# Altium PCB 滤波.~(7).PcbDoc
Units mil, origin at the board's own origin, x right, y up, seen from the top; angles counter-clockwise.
Board outline 6000 x 4000 mil, 2 copper layers (Top Layer, Bottom Layer); 19 components, 13 nets, 56 pads, 2 vias.
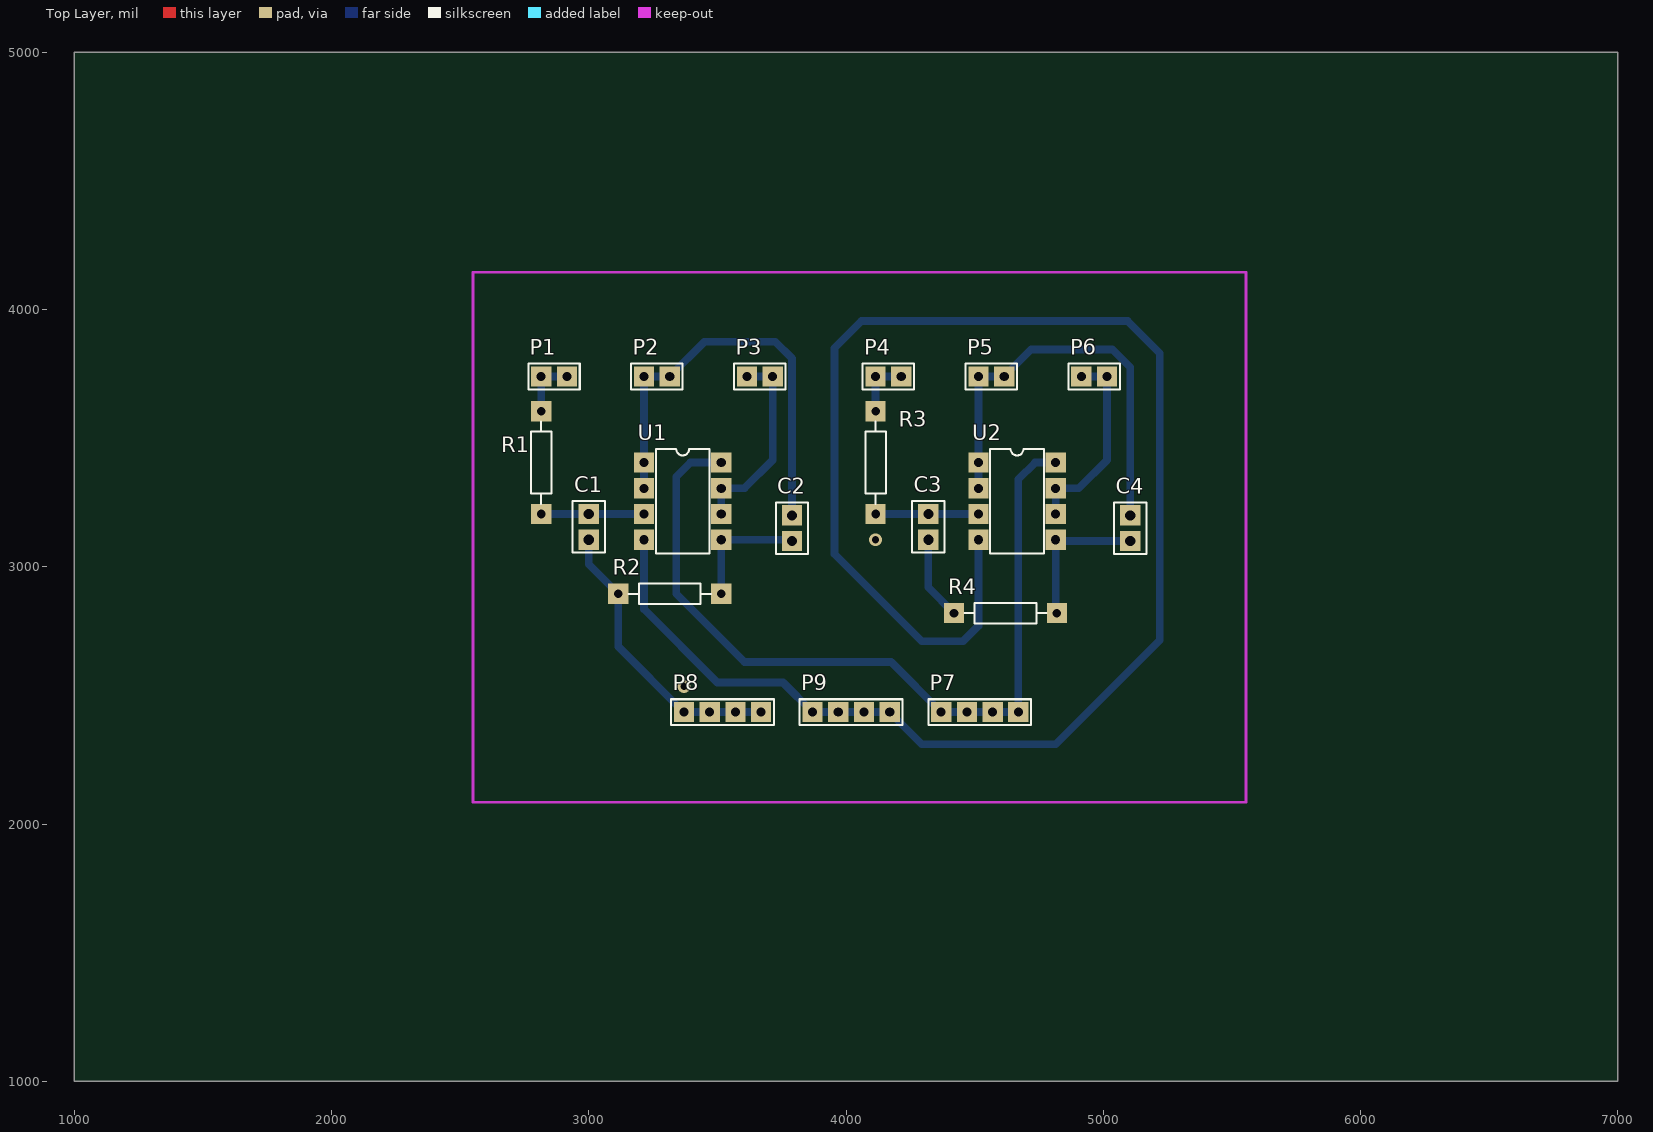
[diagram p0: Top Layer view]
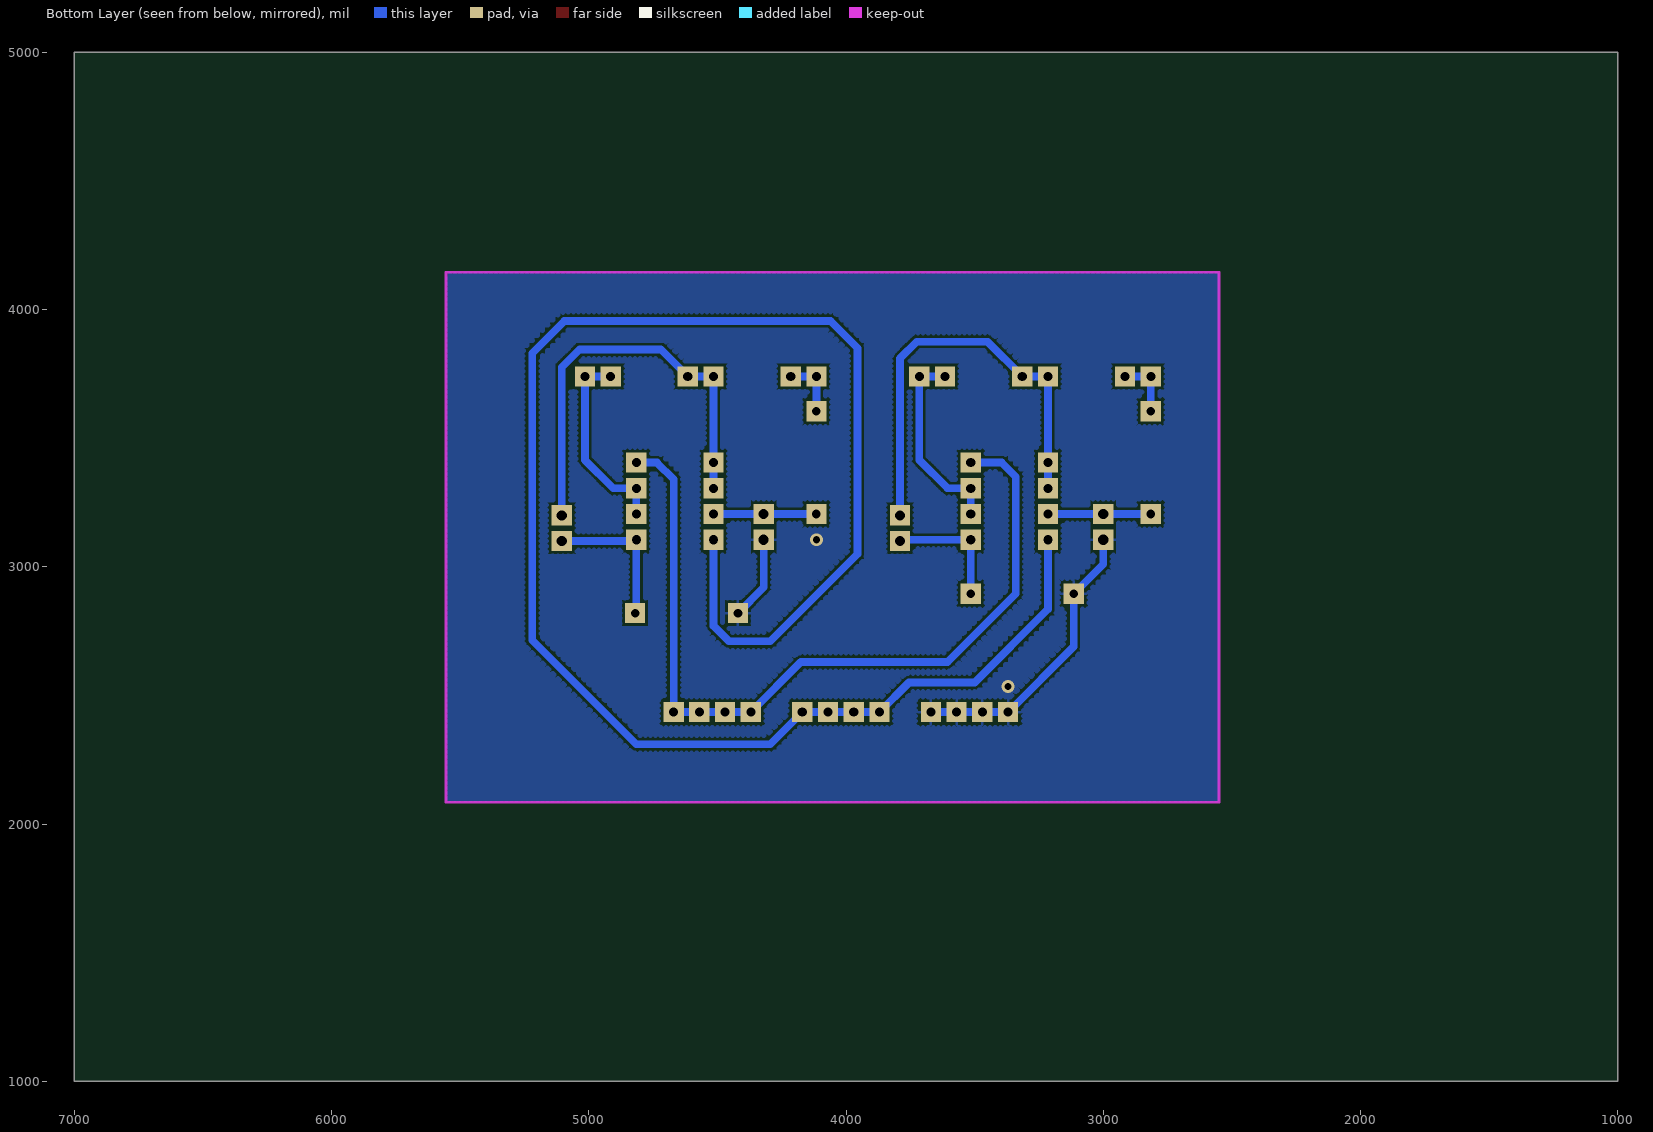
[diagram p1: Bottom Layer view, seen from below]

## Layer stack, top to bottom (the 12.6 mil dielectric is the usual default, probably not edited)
Top Layer: signal copper 1.4
Dielectric: dielectric 12.6, FR-4, Dk 4.8
Bottom Layer: signal copper 1.4

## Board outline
1000,1000 7000,1000 7000,5000 1000,5000

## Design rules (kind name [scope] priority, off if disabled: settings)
Clearance [All] p1: gap=10
PolygonConnect [All] p1: connectstyle=Relief reliefconductorwidth=10 reliefentries=4 polygonreliefangle="90 Angle" airgapwidth=10
RoutingLayers [All] p1: top layer_v5=FALSE bottom layer_v5=TRUE
RoutingVias [All] p1: holewidth=28 width=50 viastyle="Through Hole" minholewidth=28 minwidth=50 maxholewidth=28 maxwidth=50
SolderMaskExpansion [All] p1: expansion=4
Width [All] p1: maxlimit=30 minlimit=30 preferedwidth=30
27 further rules are at their usual default settings.

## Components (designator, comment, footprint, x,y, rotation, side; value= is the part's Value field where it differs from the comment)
C1 "Cap" CAPR2.54-5.1x3.2 3000,3155 r90 top
C2 "Cap" CAPR2.54-5.1x3.2 3790,3150 r270 top
C3 "Cap" CAPR2.54-5.1x3.2 4320,3155 r90 top
C4 "Cap" CAPR2.54-5.1x3.2 5105,3150 r270 top
P1 "Header 2" HDR1X2 2815,3740 r0 top
P2 "Header 2" HDR1X2 3215,3740 r0 top
P3 "Header 2" HDR1X2 3715,3740 r180 top
P4 "Header 2" HDR1X2 4215,3740 r180 top
P5 "Header 2" HDR1X2 4615,3740 r180 top
P6 "Header 2" HDR1X2 5015,3740 r180 top
P7 "Header 4" HDR1X4 4670,2435 r180 top
P8 "Header 4" HDR1X4 3670,2435 r180 top
P9 "Header 4" HDR1X4 4170,2435 r180 top
R1 "Res2" AXIAL-0.4 2815,3405 r270 top
R2 "Res2" AXIAL-0.4 3315,2895 r0 top
R3 "Res2" AXIAL-0.4 4115,3405 r270 top
R4 "Res2" AXIAL-0.4 4620,2820 r0 top
U1 "LM358N" 626-05 3365,3255 r270 top
U2 "LM358N" 626-05 4665,3255 r270 top

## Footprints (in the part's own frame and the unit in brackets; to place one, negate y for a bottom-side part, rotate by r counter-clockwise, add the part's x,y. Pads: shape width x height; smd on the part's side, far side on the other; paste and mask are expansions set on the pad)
626-05 [mm] "DIP; 8 Leads; Row Spacing 7.62 mm; Pitch 2.54 mm"
  rect 2x2 hole 0.9: 1(-3.81,-3.81) 2(-1.27,-3.81) 3(1.27,-3.81) 4(3.81,-3.81) 5(3.81,3.81) 6(1.27,3.81) 7(-1.27,3.81) 8(-3.81,3.81)
  silkscreen extent -5.15,-2.65 5.15,2.65
AXIAL-0.4 [mm] "Axial Device, Thru-Hole; 2 Leads; 0.4 in Pin Spacing"
  rect 2x2 hole 0.85: 1(-5.08,0) 2(5.08,0)
  silkscreen extent -4.06,-1.02 4.06,1.02
CAPR2.54-5.1x3.2 [mm] "Capacitor, Ceramic, Thru-Hole, Dipped Radial; Body 5.1 x 3.2 mm (WxT) Pin Spacing 2.54 mm (typ)"
  rect 2x2 hole 1: 1(-1.27,0) 2(1.27,0)
  silkscreen extent -2.55,-1.6 2.55,1.6
HDR1X2 [mm] "Connector; Header; 2 Position"
  rect 2x2 hole 0.9: 1(0,0) 2(2.54,0)
  silkscreen extent -1.27,-1.27 3.81,1.27
HDR1X4 [mm] "Connector; Header; 4 Position"
  rect 2x2 hole 0.9: 1(0,0) 2(2.54,0) 3(5.08,0) 4(7.62,0)
  silkscreen extent -1.27,-1.27 8.89,1.27

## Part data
C1 C2 C3 C4: "Capacitor"
P1 P2 P3 P4 P5 P6: "Header, 2-Pin"
P7 P8 P9: "Header, 4-Pin"
R1 R2 R3 R4: "Resistor"
U1 U2: "Dual Low-Power Operational Amplifier"

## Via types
v1: diameter 50, hole 28, Top Layer to Bottom Layer, 2 vias

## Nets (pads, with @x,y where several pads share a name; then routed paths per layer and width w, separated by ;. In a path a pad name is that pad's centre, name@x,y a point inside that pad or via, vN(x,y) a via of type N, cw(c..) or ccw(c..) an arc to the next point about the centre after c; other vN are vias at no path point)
-5: P9.1 P9.2 P9.3 P9.4 U1.4 U2.4 | length 6996.2
  Bottom Layer w30: U1.4 3215,2835 3500,2550 3755,2550 P9.4 P9.3 P9.2 P9.1 4295,2310 4815,2310 5220,2715 5220,3830 5095,3955 4060,3955 3955,3850 3955,3050 4295,2710 4455,2710 4515,2770 U2.4
GND: C1.1 C3.1 P8.1 P8.2 P8.3 P8.4 R2.1 R4.1 | length 1449.7
  Bottom Layer w30: C1.1 3000,3010 R2.1 3115,2690 P8.4 P8.3 P8.2 P8.1 ; C3.1 4320,2920 R4.1
  other v1: 3370,2535 4115,3105
NetC1_2: C1.2 R1.2 U1.3 | length 400
  Bottom Layer w30: R1.2 C1.2 U1.3
NetC2_1: C2.1 P2.1 P2.2 U1.1 U1.2 | length 1702.8
  Bottom Layer w30: U1.2 U1.1 P2.1 P2.2 3450,3875 3725,3875 3790,3810 C2.1
NetC2_2: C2.2 R2.2 U1.5 | length 480
  Bottom Layer w30: R2.2 U1.5 C2.2@3785,3105
NetC3_2: C3.2 R3.2 U2.3 | length 400
  Bottom Layer w30: R3.2 C3.2 U2.3
NetC4_1: C4.1 P5.1 P5.2 U2.1 U2.2 | length 1672.5
  Bottom Layer w30: U2.2 U2.1 P5.2 P5.1 4720,3845 5035,3845 5105,3775 C4.1
NetC4_2: C4.2 R4.2 U2.5 | length 565
  Bottom Layer w30: R4.2@4815,2825 U2.5 ; U2.5@4820,3100 C4.2
NetP1_1: P1.1 P1.2 R1.1 | length 235
  Bottom Layer w30: R1.1 P1.1 P1.2
NetP3_1: P3.1 P3.2 U1.6 U1.7 | length 770.6
  Bottom Layer w30: U1.6 U1.7 3605,3305 3715,3415 P3.1 P3.2
NetP4_1: P4.1 P4.2 R3.1 | length 235
  Bottom Layer w30: R3.1 P4.2 P4.1
NetP6_1: P6.1 P6.2 U2.6 U2.7 | length 770.6
  Bottom Layer w30: U2.6 U2.7 4905,3305 5015,3415 P6.1 P6.2
VCC: P7.1 P7.2 P7.3 P7.4 U1.8 U2.8 | length 3250.2
  Bottom Layer w30: U1.8 3395,3405 3340,3350 3340,2895 3605,2630 4175,2630 P7.4 P7.3 P7.2 P7.1 4670,3340 4735,3405 U2.8

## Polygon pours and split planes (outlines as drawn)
GND on Bottom Layer "Top Layer-No Net" (hatched 90Degree grid 20 track 20, pour order 6): 2560,4135 5545,4135 5545,2095 2560,2095

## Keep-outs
Keep-Out Layer:
  lines w10: 2550,2085 2550,4145 5555,4145 5555,2085 2550,2085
